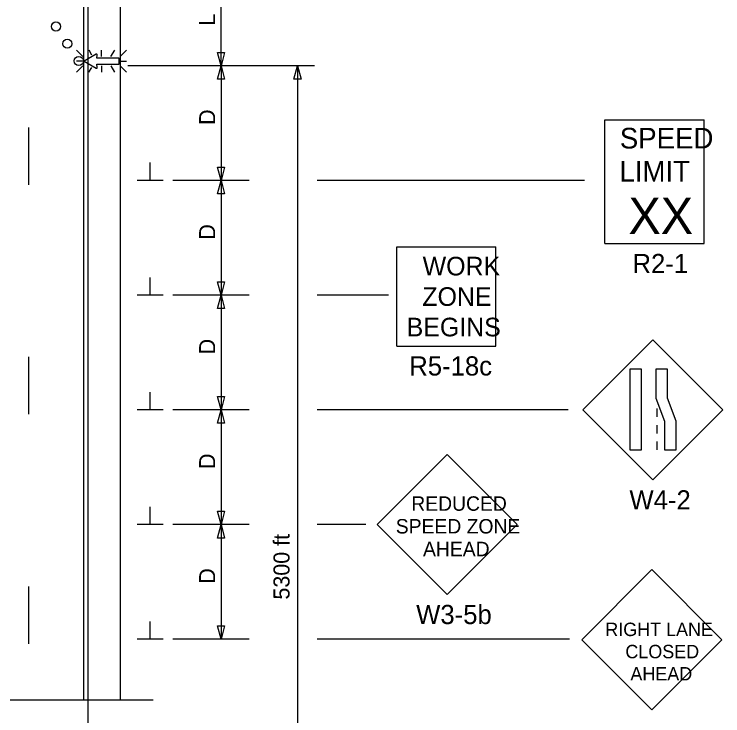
# Model space of a CAD drawing. Extents: x 16740 to 18479, y 5932 to 6964.
# Drawn here: x 16970.5 to 17279.5, y 6339.8 to 6645.7 of the extents above; entities that cross this region are included whole.
import ezdxf

# ---------------------------------------------------------------- set-up
doc = ezdxf.new("R2010")
doc.units = 0
for name, color, linetype in [('ALI_LEGAL_EX', 7, 'Continuous'), ('PAVT_EDGE_EX', 7, 'Continuous'), ('TRAFFIC_SIGNS_PR', 7, 'Continuous'), ('TYPICAL_TEXT_DIMEN_PR', 7, 'Continuous')]:
    doc.layers.add(name, color=color, linetype=linetype)

msp = doc.modelspace()

# ---------------------------------------------------------------- linework, layer by layer
at = {"layer": 'ALI_LEGAL_EX'}
msp.add_line((17002.72, 6964.07), (17002.72, 6147.1), dxfattribs=at)
for points in [[(16976.72, 6596.22), (16976.72, 6571.22)], [(16976.72, 6496.22), (16976.72, 6471.22)], [(16976.72, 6396.22), (16976.72, 6371.22)]]:
    msp.add_lwpolyline(points, dxfattribs=at)
at = {"layer": 'PAVT_EDGE_EX'}
for p, q in [((17000.72, 6926.76), (17000.72, 6346.64)), ((17016.72, 6926.76), (17016.72, 6346.64))]:
    msp.add_line(p, q, dxfattribs=at)
at = {"layer": 'TRAFFIC_SIGNS_PR'}
for p, q in [((16997.71, 6630.03), (17000.53, 6627.21)), ((17004.43, 6627.85), (17003.17, 6630.03)), ((17008.61, 6627.21), (17008.61, 6630.03)), ((17012.75, 6627.21), (17014.38, 6630.03)), ((17016.7, 6627.21), (17019.52, 6630.03)), ((17000.53, 6625.18), (16997.71, 6625.18)), ((17016.7, 6625.18), (17019.52, 6625.18)), ((16997.71, 6620.33), (17000.53, 6623.15)), ((17003.15, 6620.33), (17004.35, 6622.42)), ((17008.61, 6623.15), (17008.61, 6620.33)), ((17014.4, 6620.33), (17012.77, 6623.15)), ((17016.7, 6623.15), (17019.52, 6620.33)), ((17228.1, 6599.64), (17271.3, 6599.64)), ((17228.1, 6545.64), (17228.1, 6599.64)), ((17271.3, 6545.64), (17271.3, 6599.64)), ((17137.38, 6500.99), (17137.38, 6544.19)), ((17137.38, 6544.19), (17180.58, 6544.19)), ((17180.58, 6500.99), (17180.58, 6544.19)), ((17228.1, 6545.64), (17271.3, 6545.64)), ((17137.38, 6500.99), (17180.58, 6500.99)), ((17248.95, 6503.69), (17218.41, 6473.14)), ((17279.5, 6473.14), (17248.95, 6503.69)), ((17218.41, 6473.14), (17248.95, 6442.6)), ((17248.95, 6442.6), (17279.5, 6473.14)), ((17250.8, 6473.7), (17250.8, 6470.1)), ((17250.8, 6466.5), (17250.8, 6462.9)), ((17250.8, 6459.3), (17250.8, 6455.7)), ((17159.35, 6453.73), (17128.81, 6423.18)), ((17189.9, 6423.18), (17159.35, 6453.73)), ((17128.81, 6423.18), (17159.35, 6392.64)), ((17159.35, 6392.64), (17189.9, 6423.18)), ((17248.58, 6403.52), (17218.04, 6372.97)), ((17279.13, 6372.97), (17248.58, 6403.52)), ((17218.04, 6372.97), (17248.58, 6342.43)), ((17248.58, 6342.43), (17279.13, 6372.97))]:
    msp.add_line(p, q, dxfattribs=at)
for points in [[(17006.29, 6628.2), (17000.98, 6625.18), (17006.29, 6622.14)], [(17006.79, 6622.5), (17006.56, 6623.8), (17016.28, 6623.8), (17016.28, 6626.54), (17006.56, 6626.54), (17006.79, 6627.84)]]:
    msp.add_lwpolyline(points, dxfattribs=at)
for points in [[(17238.95, 6490.85), (17238.95, 6455.7), (17244, 6455.7), (17244, 6490.85)], [(17250.35, 6490.85), (17250.35, 6478.27), (17254.11, 6468.28), (17254.11, 6455.7), (17259.17, 6455.7), (17259.17, 6468.28), (17255.4, 6478.27), (17255.4, 6490.85)]]:
    msp.add_lwpolyline(points, close=True, dxfattribs=at)
for centre in [(16988.76, 6640.27), (16993.73, 6632.77), (16998.7, 6625.26)]:
    msp.add_circle(centre, 2, dxfattribs=at)
for centre, start, end in [((17006.45, 6627.9), 350.7308, 118.8916), ((17006.45, 6622.44), 241.4833, 9.9593)]:
    msp.add_arc(centre, 0.341, start, end, dxfattribs=at)
at = {"layer": 'TYPICAL_TEXT_DIMEN_PR'}
for p, q in [((17060.72, 6623.15), (17060.72, 6657.34)), ((17060.72, 6623.15), (17059.15, 6629.01)), ((17059.15, 6629.01), (17060.72, 6629.01)), ((17060.72, 6629.01), (17062.29, 6629.01)), ((17062.29, 6629.01), (17060.72, 6623.15)), ((17101.49, 6623.15), (17020.02, 6623.15)), ((17065.72, 6623.15), (17020.02, 6623.15)), ((17059.15, 6617.29), (17060.72, 6623.15)), ((17060.72, 6623.15), (17060.72, 6573.15)), ((17060.72, 6623.15), (17062.29, 6617.29)), ((17092.53, 6617.29), (17094.11, 6623.15)), ((17094.11, 6623.15), (17095.68, 6617.29)), ((17094.11, 6623.15), (17094.11, 6282.38)), ((17060.72, 6617.29), (17059.15, 6617.29)), ((17062.29, 6617.29), (17060.72, 6617.29)), ((17094.11, 6617.29), (17092.53, 6617.29)), ((17095.68, 6617.29), (17094.11, 6617.29)), ((17029.85, 6573.15), (17029.85, 6580.93)), ((17060.72, 6573.15), (17059.15, 6579.01)), ((17059.15, 6579.01), (17060.72, 6579.01)), ((17060.72, 6579.01), (17062.29, 6579.01)), ((17062.29, 6579.01), (17060.72, 6573.15)), ((17035.47, 6573.15), (17024.22, 6573.15)), ((17072.94, 6573.15), (17039.72, 6573.15)), ((17059.15, 6567.29), (17060.72, 6573.15)), ((17060.72, 6573.15), (17060.72, 6523.15)), ((17060.72, 6573.15), (17062.29, 6567.29)), ((17219.2, 6573.15), (17102.67, 6573.15)), ((17060.72, 6567.29), (17059.15, 6567.29)), ((17062.29, 6567.29), (17060.72, 6567.29)), ((17029.85, 6523.15), (17029.85, 6530.93)), ((17060.72, 6523.15), (17059.15, 6529.01)), ((17059.15, 6529.01), (17060.72, 6529.01)), ((17060.72, 6529.01), (17062.29, 6529.01)), ((17062.29, 6529.01), (17060.72, 6523.15)), ((17035.47, 6523.15), (17024.22, 6523.15)), ((17072.94, 6523.15), (17039.72, 6523.15)), ((17059.15, 6517.29), (17060.72, 6523.15)), ((17060.72, 6523.15), (17060.72, 6473.15)), ((17060.72, 6523.15), (17062.29, 6517.29)), ((17133.75, 6523.15), (17102.67, 6523.15)), ((17060.72, 6517.29), (17059.15, 6517.29)), ((17062.29, 6517.29), (17060.72, 6517.29)), ((17029.85, 6473.15), (17029.85, 6480.93)), ((17060.72, 6473.15), (17059.15, 6479.01)), ((17059.15, 6479.01), (17060.72, 6479.01)), ((17060.72, 6479.01), (17062.29, 6479.01)), ((17062.29, 6479.01), (17060.72, 6473.15)), ((17035.47, 6473.15), (17024.22, 6473.15)), ((17072.94, 6473.15), (17039.72, 6473.15)), ((17059.15, 6467.29), (17060.72, 6473.15)), ((17060.72, 6473.15), (17060.72, 6423.15)), ((17060.72, 6473.15), (17062.29, 6467.29)), ((17212.03, 6473.15), (17102.67, 6473.15)), ((17060.72, 6467.29), (17059.15, 6467.29)), ((17062.29, 6467.29), (17060.72, 6467.29)), ((17029.85, 6423.15), (17029.85, 6430.93)), ((17060.72, 6423.15), (17059.15, 6429.01)), ((17059.15, 6429.01), (17060.72, 6429.01)), ((17060.72, 6429.01), (17062.29, 6429.01)), ((17062.29, 6429.01), (17060.72, 6423.15)), ((17035.47, 6423.15), (17024.22, 6423.15)), ((17072.94, 6423.15), (17039.72, 6423.15)), ((17059.15, 6417.29), (17060.72, 6423.15)), ((17060.72, 6423.15), (17060.72, 6373.15)), ((17060.72, 6423.15), (17062.29, 6417.29)), ((17123.81, 6423.15), (17102.67, 6423.15)), ((17060.72, 6417.29), (17059.15, 6417.29)), ((17062.29, 6417.29), (17060.72, 6417.29)), ((17029.85, 6373.15), (17029.85, 6380.93)), ((17060.72, 6373.15), (17059.15, 6379.01)), ((17059.15, 6379.01), (17060.72, 6379.01)), ((17060.72, 6379.01), (17062.29, 6379.01)), ((17062.29, 6379.01), (17060.72, 6373.15)), ((17035.47, 6373.15), (17024.22, 6373.15)), ((17072.94, 6373.15), (17039.72, 6373.15)), ((17102.67, 6373.15), (17102.67, 6373.15)), ((17212.61, 6373.15), (17102.67, 6373.15)), ((17031.14, 6346.64), (16968.81, 6346.64))]:
    msp.add_line(p, q, dxfattribs=at)

# ---------------------------------------------------------------- texts
at = {"layer": 'TRAFFIC_SIGNS_PR'}
for s, height, p in [('SPEED', 9, (17234.59, 6587.1)), ('LIMIT', 9, (17234.41, 6572.7)), ('XX', 15.785, (17238.36, 6549.86)), ('R2-1', 8.37, (17240.12, 6532.77)), ('WORK', 8.119, (17148.63, 6531.77)), ('ZONE', 8.119, (17148.5, 6518.49)), ('BEGINS', 8.119, (17141.66, 6505.2)), ('R5-18c', 8.37, (17142.79, 6488.12)), ('W4-2', 8.37, (17238.78, 6429.73)), ('REDUCED', 6.3, (17143.67, 6429.16)), ('SPEED ZONE', 6.3, (17136.91, 6419.26)), ('AHEAD', 6.3, (17148.79, 6409.36)), ('W3-5b', 8.37, (17145.8, 6379.77)), ('RIGHT LANE', 5.85, (17228.25, 6374.54)), ('CLOSED', 5.85, (17237.01, 6364.87)), ('AHEAD', 5.85, (17239.2, 6355.19))]:
    msp.add_text(s, height=height, dxfattribs=at).set_placement(p)
at = {"layer": 'TYPICAL_TEXT_DIMEN_PR'}
for s, p in [('L', (17058.16, 6640.63)), ('D', (17058.16, 6597.37)), ('D', (17058.16, 6547.37)), ('D', (17058.16, 6497.37)), ('D', (17058.16, 6447.37)), ('5300 ft', (17090.59, 6390.45)), ('D', (17058.16, 6397.37))]:
    msp.add_text(s, height=7, rotation=90, dxfattribs=at).set_placement(p)

doc.saveas('drawing.dxf')
